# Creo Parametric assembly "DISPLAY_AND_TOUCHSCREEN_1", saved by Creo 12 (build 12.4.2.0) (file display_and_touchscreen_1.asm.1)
Units: Custom; MM, KILOGRAM, SECS

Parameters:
  PTC_WM_ITERATION = "0"
  PTC_WM_VERSION = "-.0"
  PTC_WM_LIFECYCLE_STATE = "In Work"
  PTC_WM_LIFECYCLE = "MO_CADDocument"
  PTC_WM_CREATED_BY = "Maximilian Roepper (Z0017RMS: MO)"
  PTC_WM_CREATED_ON = "18-Sep-26 11:36:42 AM"
  PTC_WM_MODIFIED_BY = "Maximilian Roepper (Z0017RMS: MO)"
  PTC_WM_MODIFIED_ON = "18-Sep-26 11:36:46 AM"
  PDMLINKNUMBER = "PDM000071455215"
  PTC_WM_NAME = "display_and_touchscreen_1.asm"
  PTC_WM_NUMBER = "PDM000071455215"

Other parameters: WEIGHT, WEIGHT_FACTOR, WEIGHT_ADD, MC_ERRORS, SUPPLIER, ISPOSITIONINGASSEMBLY

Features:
  1. coordinate system
  2. imported feature
  3. component "DISPLAY_1"
  4. component "TOUCHSCREEN_1"

Other named items: DRW_VIEW_ORG, ROUGH-GROB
